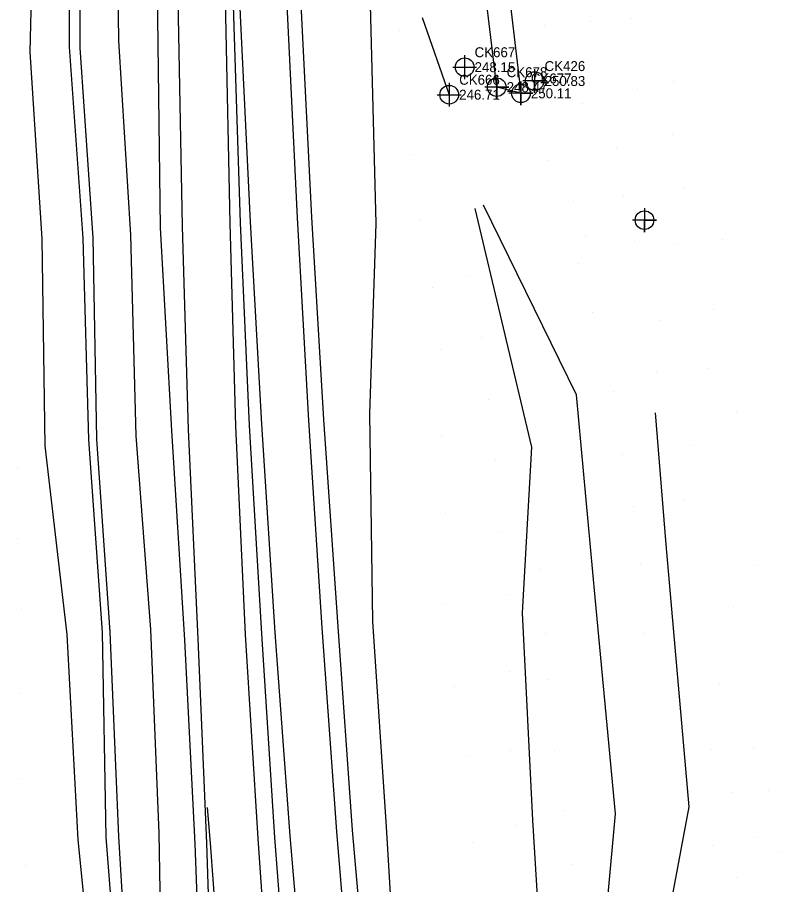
# Model space of a CAD drawing. Extents: x 1941547 to 1942851, y 663002 to 668358.
# Drawn here: x 1941913.3 to 1942104.7, y 666986.5 to 667204.6 of the extents above; entities that cross this region are included whole.
import ezdxf

# ---------------------------------------------------------------- set-up
doc = ezdxf.new("R2010")
doc.units = 0
for name, color, linetype in [('CTL NGS Vertical CELL', 7, 'Continuous'), ('Default Symbol CELL', 7, 'Continuous'), ('Exist DTM Breakline Cogo Elevation', 7, 'Continuous'), ('Exist DTM Breakline Cogo Number', 7, 'Continuous'), ('Exist DTM Breakline Cogo Point CELL', 7, 'Continuous'), ('Exist DTM Drainline Cogo Elevation', 7, 'Continuous'), ('Exist Property Iron Pin Cogo Number', 7, 'Continuous'), ('Exist Roads EOP Cogo Elevation', 7, 'Continuous'), ('Exist Roads EOP Cogo Number', 7, 'Continuous'), ('Exist Roads EOT', 7, 'Continuous'), ('Exist Utilities Telephone UG Cable SUE LOS C Cogo Elevation', 7, 'Continuous'), ('Exist Utilities Telephone UG FO SUE LOS C Cogo Elevation', 7, 'Continuous'), ('PH Exist DTM Point', 7, 'Continuous')]:
    doc.layers.add(name, color=color, linetype=linetype)

msp = doc.modelspace()

# ---------------------------------------------------------------- linework, layer by layer
at = {"layer": 'CTL NGS Vertical CELL'}
for points in [[(1941944.36, 666841.1), (1941940.55, 666899.2), (1941939.33, 666951.2), (1941935.62, 666998.45), (1941934.74, 667049.89), (1941931.25, 667098.44), (1941929.85, 667149.11), (1941926.42, 667197.25), (1941926.31, 667249.1), (1941924.77, 667298.53), (1941926.78, 667349), (1941928.74, 667400.53)], [(1941946.98, 666841.87), (1941943.17, 666899.66), (1941941.62, 666951.26), (1941938.82, 666998.62), (1941936.61, 667049.98), (1941933.24, 667098.55), (1941932.35, 667149.21), (1941929.12, 667196.95), (1941929.17, 667249.39), (1941928.09, 667298.81), (1941929.02, 667349.18), (1941930.48, 667400.62)]]:
    msp.add_lwpolyline(points, dxfattribs=at)
at = {"layer": 'Exist DTM Breakline Cogo Number'}
for points in [[(1942025.76, 667195.1), (1942025.76, 667192.1)], [(1942022.76, 667192.1), (1942025.76, 667192.1)], [(1942025.76, 667192.1), (1942028.76, 667192.1)], [(1942025.76, 667192.1), (1942025.76, 667189.1)], [(1942021.88, 667188.17), (1942021.88, 667185.17)], [(1942018.88, 667185.17), (1942021.88, 667185.17)], [(1942021.88, 667185.17), (1942024.88, 667185.17)], [(1942021.88, 667185.17), (1942021.88, 667182.17)]]:
    msp.add_lwpolyline(points, dxfattribs=at)
for centre in [(1942025.76, 667192.1), (1942021.88, 667185.17)]:
    msp.add_circle(centre, 2.34, dxfattribs=at)
at = {"layer": 'Exist DTM Drainline Cogo Elevation'}
msp.add_lwpolyline([(1942070.97, 667156.61), (1942070.97, 667150.61), (1942070.97, 667153.61), (1942073.97, 667153.61), (1942067.97, 667153.61)], dxfattribs=at)
msp.add_circle((1942070.97, 667153.61), 2.34, dxfattribs=at)
at = {"layer": 'Exist Property Iron Pin Cogo Number'}
msp.add_lwpolyline([(1942008.85, 666690.79), (1942002.07, 666741.6), (1941996.47, 666793.56), (1941990.89, 666844.38), (1941986.33, 666894.98), (1941981.96, 666947.23), (1941978.03, 666998.38), (1941974.77, 667049.54), (1941971.64, 667101.97), (1941969.4, 667152.95), (1941967.69, 667204.95), (1941966.16, 667257.35), (1941965.22, 667309.63), (1941964.5, 667362.27), (1941964.07, 667413.88)], dxfattribs=at)
at = {"layer": 'Exist Roads EOP Cogo Number'}
for points in [[(1942043.36, 667191.62), (1942043.36, 667185.62), (1942043.36, 667188.62), (1942046.36, 667188.62), (1942040.36, 667188.62)], [(1942033.83, 667190.08), (1942033.83, 667184.08), (1942033.83, 667187.08), (1942036.83, 667187.08), (1942030.83, 667187.08)], [(1942039.91, 667188.52), (1942039.91, 667182.52), (1942039.91, 667185.52), (1942042.91, 667185.52), (1942036.91, 667185.52)]]:
    msp.add_lwpolyline(points, dxfattribs=at)
for centre in [(1942043.36, 667188.62), (1942033.83, 667187.08), (1942039.91, 667185.52)]:
    msp.add_circle(centre, 2.34, dxfattribs=at)
at = {"layer": 'Exist Roads EOT'}
for points in [[(1941951.98, 667413.81), (1941952.26, 667362.04), (1941952.46, 667308.89), (1941952.97, 667256.94), (1941953.75, 667204.68), (1941954.75, 667152.02), (1941956.26, 667100.95), (1941958.71, 667048.32), (1941960.84, 666996.9), (1941962.55, 666945.54), (1941964.6, 666892.87), (1941965.91, 666841.69), (1941967.14, 666790.13), (1941967.35, 666775.96), (1941965.99, 666756.26), (1941960.31, 666738.22), (1941950.2, 666725.25), (1941933.38, 666712.58), (1941911.61, 666702.83), (1941884.69, 666696.42), (1941884.07, 666696.32)], [(1942026.6, 666693.52), (1942019.88, 666743.94), (1942013.54, 666795.86), (1942007.82, 666846.76), (1942002.76, 666897.1), (1941997.85, 666949.23), (1941993.62, 666999.88), (1941989.95, 667051.06), (1941986.57, 667103.22), (1941983.76, 667154.19), (1941981.25, 667205.98), (1941979.11, 667258.1), (1941977.64, 667310.25), (1941976.44, 667362.8), (1941975.95, 667413.99)], [(1942003.35, 666690.27), (1941996.18, 666740.71), (1941990.55, 666792.95), (1941985.7, 666843.93), (1941981.39, 666894.52), (1941977.35, 666947.08), (1941973.82, 666998.13), (1941970.64, 667049.39), (1941968.27, 667101.82), (1941966.8, 667152.88), (1941965.74, 667205.04), (1941965, 667257.27), (1941964.59, 667309.55), (1941964.7, 667315.61)], [(1942014.4, 666691.83), (1942008.07, 666742.35), (1942001.91, 666794.2), (1941996.25, 666845.1), (1941991.05, 666895.6), (1941986.23, 666947.8), (1941981.87, 666998.75), (1941978.14, 667049.88), (1941974.78, 667102.32), (1941971.91, 667153.2), (1941969.44, 667205.09), (1941967.31, 667257.47), (1941965.84, 667309.66), (1941965.66, 667315.58)], [(1941999.64, 666628.44), (1941991.02, 666686.62), (1941984.46, 666738.66), (1941978.51, 666791.44), (1941973.56, 666842.31), (1941969.71, 666892.89), (1941965.59, 666945.78), (1941961.89, 666996.94), (1941961.07, 667005.9)]]:
    msp.add_lwpolyline(points, dxfattribs=at)
at = {"layer": 'Exist Utilities Telephone UG Cable SUE LOS C Cogo Elevation'}
for points in [[(1941947.53, 667413.75), (1941946.96, 667361.74), (1941947.54, 667308.73), (1941948.08, 667256.56), (1941948.52, 667204.49), (1941949.24, 667151.67), (1941952.06, 667100.74), (1941955.32, 667048.01), (1941957.95, 666996.74), (1941959.85, 666945.25), (1941962.44, 666892.69), (1941963.58, 666841.54), (1941964.58, 666789.92), (1941964.71, 666776.07), (1941964.25, 666756.23), (1941958.52, 666739.42), (1941948.3, 666727.6), (1941930.93, 666716.38), (1941910.35, 666706.81), (1941883.98, 666699.72), (1941884.18, 666697.45), (1941835.96, 666689.1), (1941789.23, 666683.83)], [(1942029.9, 666693.84), (1942023.63, 666744.48), (1942017.17, 666796.27), (1942011.56, 666847.08), (1942006.59, 666897.47), (1942002, 666949.63), (1941997.54, 667000.16), (1941993.96, 667051.35), (1941990.36, 667103.49), (1941987.34, 667154.41), (1941984.74, 667206.16), (1941982.79, 667258.26), (1941981.31, 667310.45), (1941980.08, 667362.7), (1941979.57, 667414.02)], [(1942029.9, 666693.84), (1942023.63, 666744.48), (1942017.17, 666796.27), (1942011.56, 666847.08), (1942006.59, 666897.47), (1942002, 666949.63), (1941997.54, 667000.16), (1941993.96, 667051.35), (1941990.36, 667103.49), (1941987.34, 667154.41), (1941984.74, 667206.16), (1941982.79, 667258.26), (1941981.31, 667310.45), (1941980.08, 667362.7), (1941979.57, 667414.02)]]:
    msp.add_lwpolyline(points, dxfattribs=at)
at = {"layer": 'Exist Utilities Telephone UG FO SUE LOS C Cogo Elevation'}
for points in [[(1941953.68, 666843.33), (1941951.66, 666900.41), (1941949.77, 666951.26), (1941948.98, 666999.44), (1941946.86, 667050.67), (1941943.18, 667099.35), (1941941.85, 667149.88), (1941938.77, 667198.77), (1941938.16, 667249.33), (1941936.9, 667299.38), (1941937.19, 667349.01), (1941938.12, 667401.41), (1941938.73, 667423.66)], [(1941940.44, 666840.55), (1941933.09, 666898.2), (1941933.3, 666950.95), (1941928.6, 666997.79), (1941925.81, 667049.37), (1941920.3, 667096.89), (1941919.5, 667148.93), (1941916.49, 667195.96), (1941917.83, 667250.95), (1941915.62, 667297.28), (1941918.48, 667349.12), (1941919.21, 667400.3)], [(1942031.05, 667292.59), (1942030.82, 667282.64), (1942030.85, 667254.33), (1942032.79, 667232.89), (1942036.84, 667211.09), (1942039.91, 667185.52), (1942033.83, 667187.08), (1942031.13, 667209.41), (1942029.96, 667231.76)], [(1942032.72, 666744.96), (1942027.14, 666797.25), (1942020.56, 666847.68), (1942015.28, 666898.21), (1942009.12, 666950.56), (1942006.12, 667001.04), (1942002.66, 667052.7), (1942001.92, 667104.94), (1942003.5, 667152.75), (1942001.89, 667214.29)], [(1942015.12, 667204.55), (1942021.88, 667185.17)], [(1942028.31, 667156.54), (1942042.56, 667096.56), (1942040.21, 667054.82), (1942042.82, 667002.69), (1942045.48, 666958.9), (1942042.61, 666943.17)], [(1942060.3, 666945.61), (1942060.11, 666964.77), (1942063.7, 667004.29), (1942058.57, 667058.69), (1942053.87, 667109.65), (1942030.5, 667157.36)], [(1942073.68, 667105.13), (1942076.31, 667072.07), (1942082.11, 667006.08), (1942073.62, 666960.77), (1942080.21, 666930.55)]]:
    msp.add_lwpolyline(points, dxfattribs=at)
at = {"layer": 'PH Exist DTM Point'}
for p, q in [((1942057.46, 667203.58), (1942057.46, 667203.58)), ((1942067.63, 667204.27), (1942067.63, 667204.27)), ((1942009.29, 667201.32), (1942009.29, 667201.32)), ((1942045.83, 667202.63), (1942045.83, 667202.63)), ((1942078.28, 667188.37), (1942078.28, 667188.37)), ((1942069.32, 667186.36), (1942069.32, 667186.36)), ((1942055.43, 667182.95), (1942055.43, 667182.95)), ((1942077.94, 667175.16), (1942077.94, 667175.16)), ((1942064.04, 667171.75), (1942064.04, 667171.75)), ((1942012.02, 667170.04), (1942012.02, 667170.04)), ((1942046.82, 667168.71), (1942046.82, 667168.71)), ((1942065.79, 667159.68), (1942065.79, 667159.68)), ((1942080.89, 667161.78), (1942080.89, 667161.78)), ((1942053.07, 667158.43), (1942053.07, 667158.43)), ((1942014.33, 667153.45), (1942014.33, 667153.45)), ((1942056.12, 667149.7), (1942056.12, 667149.7)), ((1942068.58, 667148.36), (1942068.58, 667148.36)), ((1942079.29, 667147.42), (1942079.29, 667147.42)), ((1942090.55, 667148.69), (1942090.55, 667148.69)), ((1942054.38, 667142.8), (1942054.38, 667142.8)), ((1942027.03, 667139.56), (1942027.03, 667139.56)), ((1942017.62, 667136.64), (1942017.62, 667136.64)), ((1942057.85, 667130.38), (1942057.85, 667130.38)), ((1942088.23, 667131.25), (1942088.23, 667131.25)), ((1942075.03, 667128.37), (1942075.03, 667128.37)), ((1942030.08, 667124.06), (1942030.08, 667124.06)), ((1942019.79, 667121.01), (1942019.79, 667121.01)), ((1942086.84, 667116.33), (1942086.84, 667116.33)), ((1942074.11, 667115.27), (1942074.11, 667115.27)), ((1942063.15, 667110.58), (1942063.15, 667110.58)), ((1942031.64, 667108.61), (1942031.64, 667108.61)), ((1942094, 667105.38), (1942094, 667105.38)), ((1942019.92, 667099.5), (1942019.92, 667099.5)), ((1942083.22, 667096.94), (1942083.22, 667096.94)), ((1942065.55, 667094.67), (1942065.55, 667094.67)), ((1942033.4, 667093.48), (1942033.4, 667093.48)), ((1941913.38, 667091.48), (1941913.38, 667091.48)), ((1942080.91, 667083.44), (1942080.91, 667083.44)), ((1942068.14, 667081.53), (1942068.14, 667081.53)), ((1942021.03, 667079.92), (1942021.03, 667079.92)), ((1942035.07, 667075.43), (1942035.07, 667075.43)), ((1941913.4, 667073.54), (1941913.4, 667073.54)), ((1942069.86, 667066.91), (1942069.86, 667066.91)), ((1942099.44, 667066.65), (1942099.44, 667066.65)), ((1942044.78, 667065.7), (1942044.78, 667065.7)), ((1942036.21, 667059.5), (1942036.21, 667059.5)), ((1942020.87, 667057.27), (1942020.87, 667057.27)), ((1941914.23, 667055.74), (1941914.23, 667055.74)), ((1942093.47, 667056.39), (1942093.47, 667056.39)), ((1942046.08, 667049.63), (1942046.08, 667049.63)), ((1942071.02, 667049.71), (1942071.02, 667049.71)), ((1942037.09, 667039.98), (1942037.09, 667039.98)), ((1942046.68, 667038.14), (1942046.68, 667038.14)), ((1942023.19, 667036.37), (1942023.19, 667036.37)), ((1942089.74, 667036.91), (1942089.74, 667036.91)), ((1941913.82, 667034.57), (1941913.82, 667034.57)), ((1942037.4, 667020.19), (1942037.4, 667020.19)), ((1942048.34, 667020.31), (1942048.34, 667020.31)), ((1942087.79, 667020.39), (1942087.79, 667020.39)), ((1942098.35, 667020.7), (1942098.35, 667020.7)), ((1942026.99, 667018.69), (1942026.99, 667018.69)), ((1941913.64, 667013.28), (1941913.64, 667013.28)), ((1942093.11, 667009.6), (1942093.11, 667009.6)), ((1942102.25, 667010.29), (1942102.25, 667010.29)), ((1942050.54, 667005.2), (1942050.54, 667005.2)), ((1942038.45, 667001.43), (1942038.45, 667001.43)), ((1942098.65, 666998.27), (1942098.65, 666998.27)), ((1942027.8, 666997.01), (1942027.8, 666997.01)), ((1942087.96, 666996.28), (1942087.96, 666996.28)), ((1942104.71, 666994.76), (1942104.71, 666994.76)), ((1941915.29, 666991.29), (1941915.29, 666991.29)), ((1942052.86, 666991.52), (1942052.86, 666991.52)), ((1942094.15, 666988.34), (1942094.15, 666988.34))]:
    msp.add_line(p, q, dxfattribs=at)

# ---------------------------------------------------------------- texts
at = {"layer": 'Default Symbol CELL'}
for s, p in [('248.15', (1942028.26, 667190.85)), ('246.71', (1942024.38, 667183.93))]:
    msp.add_text(s, height=2.5, dxfattribs=at).set_placement(p)
at = {"layer": 'Exist DTM Breakline Cogo Elevation'}
for s, p in [('CK667', (1942028.26, 667194.6)), ('CK666', (1942024.38, 667187.68))]:
    msp.add_text(s, height=2.5, dxfattribs=at).set_placement(p)
at = {"layer": 'Exist DTM Breakline Cogo Point CELL'}
for s, p in [('248.47', (1942036.33, 667185.83)), ('250.83', (1942045.86, 667187.37)), ('250.11', (1942042.41, 667184.27))]:
    msp.add_text(s, height=2.5, dxfattribs=at).set_placement(p)
at = {"layer": 'Exist Roads EOP Cogo Elevation'}
for s, p in [('CK426', (1942045.86, 667191.12)), ('CK678', (1942036.33, 667189.58)), ('CK677', (1942042.41, 667188.02))]:
    msp.add_text(s, height=2.5, dxfattribs=at).set_placement(p)

doc.saveas('drawing.dxf')
